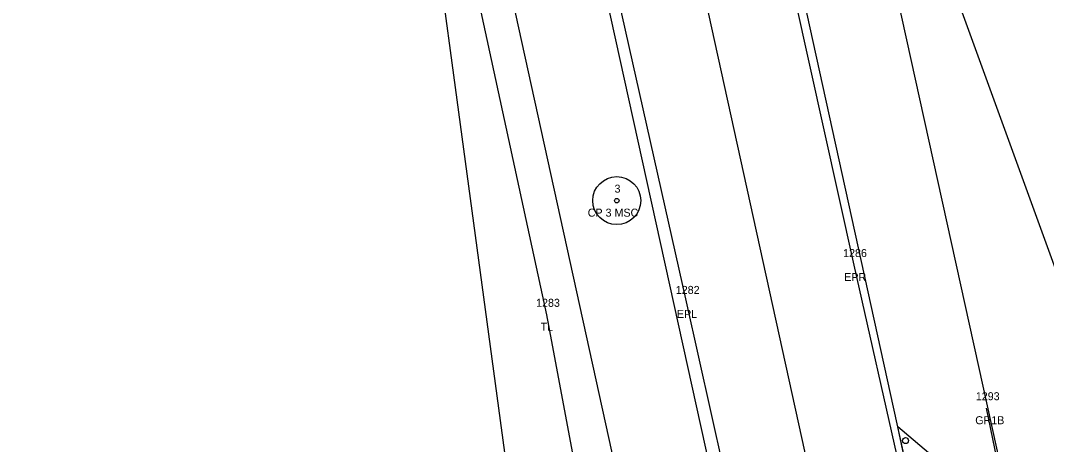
# Model space of a CAD drawing. Extents: x 2522090 to 2524658, y 882711 to 887512.
# Drawn here: x 2523667.1 to 2523795.3, y 885232.4 to 885285.4 of the extents above; entities that cross this region are included whole.
import ezdxf

# ---------------------------------------------------------------- set-up
doc = ezdxf.new("R2010")
doc.units = 0
for name, color, linetype in [('RD_EV_JurisArea', 7, 'Continuous'), ('RD_EX_GuardRail', 7, 'Continuous'), ('RD_EX_GuardRail_txCode', 7, 'Continuous'), ('RD_EX_Road', 7, 'Continuous'), ('RD_EX_Road_txCode', 7, 'Continuous'), ('RD_EX_VEG', 7, 'Continuous'), ('RD_EX_VEG_txCode', 7, 'Continuous'), ('RD_HC_Cl', 7, 'Continuous'), ('RD_HC_Data', 7, 'Continuous'), ('RD_HC_txCode', 7, 'Continuous'), ('RD_PD_Final_TrvlWay', 7, 'Continuous'), ('RD_PD_GR', 7, 'Continuous'), ('RD_PD_PaveShd', 7, 'Continuous'), ('RD_SMD_Locator', 7, 'Continuous')]:
    doc.layers.add(name, color=color, linetype=linetype)

msp = doc.modelspace()

# ---------------------------------------------------------------- linework, layer by layer
at = {"layer": 'RD_EV_JurisArea'}
for points in [[(2523761.17, 885134.03), (2523740.58, 885149.03), (2523730.55, 885209.77), (2523710.6, 885357.47), (2523698.09, 885411.19), (2523674.93, 885498.62), (2523657.6, 885564.24), (2523640.82, 885610.87), (2523583.66, 885726.91), (2523539.21, 885693.17), (2523494.42, 885646.98)], [(2523761.17, 885134.03), (2523808.21, 885149.21), (2523821.91, 885178.64), (2523802.85, 885236.55), (2523777.81, 885305.56), (2523748.2, 885444.32), (2523730.68, 885516.88), (2523708.64, 885617.3), (2523698.71, 885662.02), (2523727.83, 885665.82), (2523757.3, 885671.75)]]:
    msp.add_lwpolyline(points, dxfattribs=at)
at = {"layer": 'RD_EX_GuardRail'}
msp.add_lwpolyline([(2523803.79, 885159.91), (2523798.24, 885186.26), (2523787.8, 885236.89)], dxfattribs=at)
at = {"layer": 'RD_EX_Road'}
for p, q in [((2523771.24, 885254.79), (2523751.35, 885344.92)), ((2523750.32, 885250.18), (2523730.02, 885340.63)), ((2523792.78, 885159.31), (2523771.24, 885254.79)), ((2523771.58, 885154.56), (2523750.32, 885250.18))]:
    msp.add_line(p, q, dxfattribs=at)
at = {"layer": 'RD_EX_VEG'}
msp.add_lwpolyline([(2523749.81, 885158.06), (2523732.86, 885248.57), (2523691.62, 885438.95), (2523639.52, 885601.04)], dxfattribs=at)
at = {"layer": 'RD_HC_Cl'}
msp.add_line((2523641.17, 885794.2), (2524197.76, 883266.56), dxfattribs=at)
at = {"layer": 'RD_HC_Data'}
for radius in [3, 0.282]:
    msp.add_circle((2523741.6, 885262.84), radius, dxfattribs=at)
at = {"layer": 'RD_PD_Final_TrvlWay'}
for p, q in [((2523722.39, 885481.14), (2524037.44, 884050.42)), ((2523698.95, 885475.98), (2524014, 884045.26))]:
    msp.add_line(p, q, dxfattribs=at)
at = {"layer": 'RD_PD_GR'}
for p, q in [((2523722.6, 885533.67), (2523791.95, 885218.71)), ((2523746.05, 885208.61), (2523684.39, 885488.64))]:
    msp.add_line(p, q, dxfattribs=at)
at = {"layer": 'RD_PD_PaveShd'}
for p in [(2523783.14, 885205.25), (2523791.15, 885222.37)]:
    msp.add_line(p, (2523776.69, 885234.55), dxfattribs=at)
msp.add_circle((2523777.67, 885232.84), 0.375, dxfattribs=at)
msp.add_circle((2523777.67, 885232.84), 0.375, dxfattribs=at)
at = {"layer": 'RD_SMD_Locator'}
for centre in [(2523741.6, 885262.84), (2523771.24, 885254.79), (2523750.32, 885250.18), (2523732.86, 885248.57), (2523787.8, 885236.89)]:
    msp.add_circle(centre, 0.001, dxfattribs=at)

# ---------------------------------------------------------------- texts
at = {"layer": 'RD_EX_GuardRail_txCode'}
for s, p in [('1293', (2523786.45, 885237.89)), ('GR1B', (2523786.38, 885234.89))]:
    msp.add_text(s, height=1, dxfattribs=at).set_placement(p)
at = {"layer": 'RD_EX_Road_txCode'}
for s, p in [('1286', (2523769.87, 885255.79)), ('EPR', (2523770.01, 885252.79)), ('1282', (2523748.97, 885251.18)), ('EPL', (2523749.11, 885248.18))]:
    msp.add_text(s, height=1, dxfattribs=at).set_placement(p)
at = {"layer": 'RD_EX_VEG_txCode'}
for s, p in [('1283', (2523731.52, 885249.57)), ('TL', (2523732.09, 885246.57))]:
    msp.add_text(s, height=1, dxfattribs=at).set_placement(p)
at = {"layer": 'RD_HC_txCode'}
for s, p in [('3', (2523741.32, 885263.84)), ('CP 3 MSC', (2523737.97, 885260.84))]:
    msp.add_text(s, height=1, dxfattribs=at).set_placement(p)

doc.saveas('drawing.dxf')
